(* Logix 5000 project; controller AMCI_5034_PTO_AM_Sample vendor 1 type 14 code 190 rev 37.11; software revision 37.00; part 3 of 3 *)

ADD_ON_INSTRUCTION AMCI_5034_PTO_AM_Registration   (* revision 1.0, vendor AMCI, ExecuteEnableInFalse *)
// AMCI Registration Move
// Revision note:
// 10/1/2025 Initial release of AOI.  Making the rung false will stop the registration move
// Help:
// Performs CW or CCW Registration Moves
// AXIS INPUT DATA:  Input data from the AMCI 5034-PTO-AM.   Uses the AMCI_5034_PTO_Input_Data User Defined Data Type.
// AXIS OUTPUT DATA; Output data from the AOI to the AMCI 5034-PTO-AM.    Uses the AMCI_5034_PTO_Output_Data User Defined Data Type.
// DIRECTION: 0 for Positve CW  or 1 for Negative CCW
// REGISTRATION_DISTANCE: Distance to move after the Registration Input has become active.
// TARGETVELOCITY: Speed of move in units of steps / sec
// ACCELERATION: Acceleration Rate in units of steps / sec / ms
// DECELERATION:  Deceleration Rate in units of steps / sec / ms
// EN (Enable) Set when rung is true, Reset when rung is false
// DN (Done) Set when command is sent to the motion device.  Reset when the rung is false.
// ER (Error) Set when a command, input. or configuration error.  Reset when the rung is false.
// IP (In Process) Set when motion is occurring.   Reset when motion stops or the rung goes false.
VAR_IN_OUT
   Axis_Input_Data : AMCI_5034_PTO_AM_Input_Data; {required}
   Axis_Output_Data : AMCI_5034_PTO_AM_Output_Data; {required}
END_VAR
VAR_INPUT
   Direction_0_PositiveCW_1_NegativeCCW : BOOL; {required}   // 0=jog CW 1=jog CCW
   _0_normal_1_S_Curve_Acceleration : BOOL;
   _0_Triangular_1_Trapezoidal_S_Curve : BOOL;
   Registration_Distance : DINT; {required}
   Programmed_Speed : DINT; {required}
   Acceleration : DINT; {required}
   Deceleration : INT; {required}
END_VAR
VAR_OUTPUT
   EN : BOOL; {visible}   // set when rung with AOI is true
   DN : BOOL; {access Read Only, visible}   // set when move was succesfully initiated
   ER : BOOL; {visible}
   IP : BOOL; {visible}   // set when motion occurring
END_VAR
VAR
   command_data_block : DINT[5];
        [0]   // Command Word
        [1]   // Target Positon
        [2]   // Programmed Speed
        [3]   // Acceleration
        [4]   // Deceleration
   motion_occurring : BOOL; {access None}
   Internal_Enable : BOOL; {access None}   // set when driver ready to receive motion command
END_VAR

ROUTINE EnableInFalse   (* ladder *)
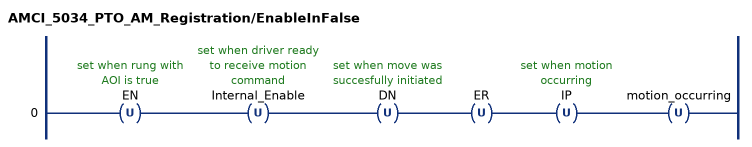
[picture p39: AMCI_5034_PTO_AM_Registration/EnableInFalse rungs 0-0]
   0: OTU(EN)OTU(Internal_Enable)OTU(DN)OTU(ER)OTU(IP)OTU(motion_occurring);
END_ROUTINE

ROUTINE Logic   (* ladder *)
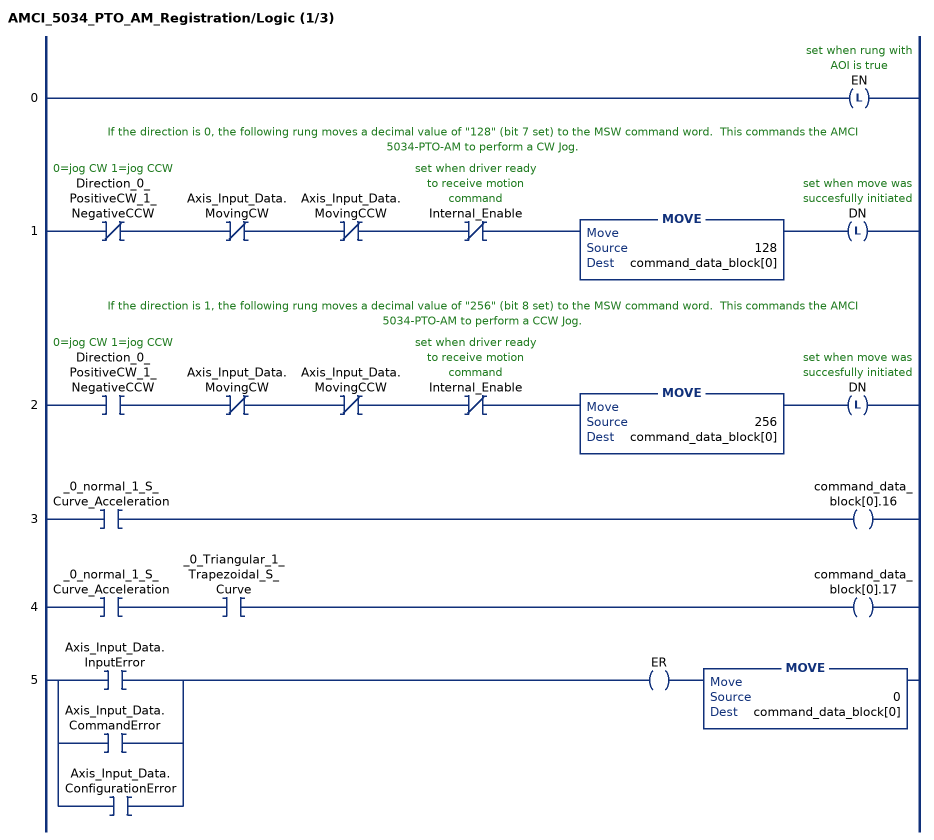
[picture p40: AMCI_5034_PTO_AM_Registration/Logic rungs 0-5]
   0: OTL(EN);
   // If the direction is 0, the following rung moves a decimal value of "128" (bit 7 set) to the MSW command word.  This commands the AMCI 5034-PTO-AM to perform a CW Jog.
   1: XIO(Direction_0_PositiveCW_1_NegativeCCW)XIO(Axis_Input_Data.MovingCW)XIO(Axis_Input_Data.MovingCCW)XIO(Internal_Enable)MOVE(128,command_data_block[0])OTL(DN);
   // If the direction is 1, the following rung moves a decimal value of "256" (bit 8 set) to the MSW command word.  This commands the AMCI 5034-PTO-AM to perform a CCW Jog.
   2: XIC(Direction_0_PositiveCW_1_NegativeCCW)XIO(Axis_Input_Data.MovingCW)XIO(Axis_Input_Data.MovingCCW)XIO(Internal_Enable)MOVE(256,command_data_block[0])OTL(DN);
   3: XIC(_0_normal_1_S_Curve_Acceleration)OTE(command_data_block[0].16);
   4: XIC(_0_normal_1_S_Curve_Acceleration)XIC(_0_Triangular_1_Trapezoidal_S_Curve)OTE(command_data_block[0].17);
   5: [XIC(Axis_Input_Data.InputError) ,XIC(Axis_Input_Data.CommandError) ,XIC(Axis_Input_Data.ConfigurationError) ]OTE(ER)MOVE(0,command_data_block[0]);
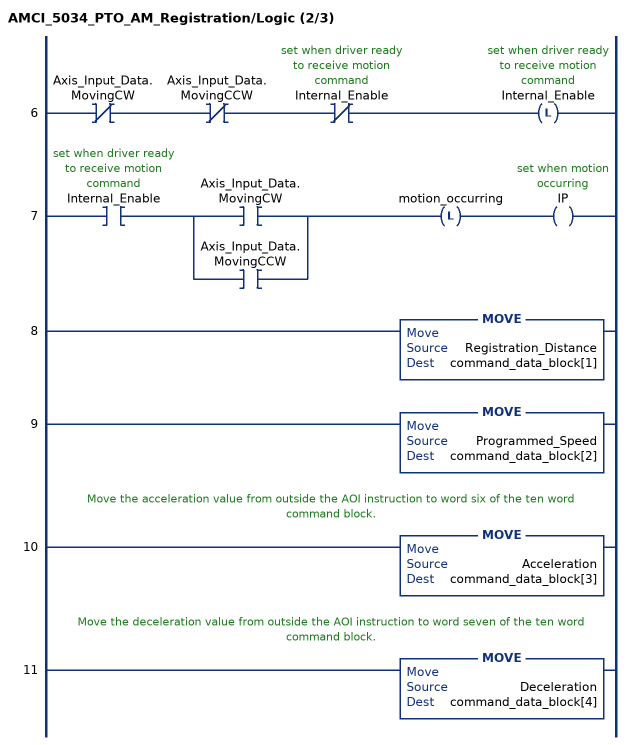
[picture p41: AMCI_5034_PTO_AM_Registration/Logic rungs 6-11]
   6: XIO(Axis_Input_Data.MovingCW)XIO(Axis_Input_Data.MovingCCW)XIO(Internal_Enable)OTL(Internal_Enable);
   7: XIC(Internal_Enable)[XIC(Axis_Input_Data.MovingCW) ,XIC(Axis_Input_Data.MovingCCW) ]OTL(motion_occurring)OTE(IP);
   8: MOVE(Registration_Distance,command_data_block[1]);
   9: MOVE(Programmed_Speed,command_data_block[2]);
   // Move the acceleration value from outside the AOI instruction to word six of the ten word command block.
   10: MOVE(Acceleration,command_data_block[3]);
   // Move the deceleration value from outside the AOI instruction to word seven of the ten word command block.
   11: MOVE(Deceleration,command_data_block[4]);
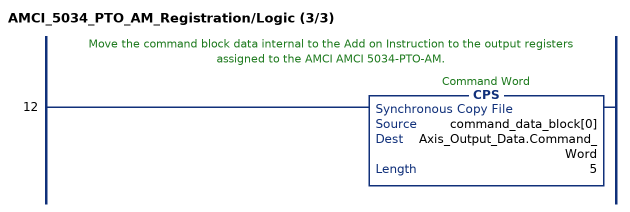
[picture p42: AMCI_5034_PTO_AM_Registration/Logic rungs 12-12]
   // Move the command block data internal to the Add on Instruction to the output registers assigned to the AMCI AMCI 5034-PTO-AM.
   12: CPS(command_data_block[0],Axis_Output_Data.Command_Word,5);
END_ROUTINE
END_ADD_ON_INSTRUCTION

ADD_ON_INSTRUCTION AMCI_5034_PTO_AM_Resume   (* revision 1.0, vendor AMCI, ExecuteEnableInFalse *)
// AMCI Resume
// Revision note:
// 10/01/2025 Initial Release
// Help:
// AXIS INPUT DATA:  Input data from the AMCI 5034-PTO-AM.   Uses the AMCI_5034_PTO_Input_Data User Defined Data Type.
// AXIS OUTPUT DATA; Output data from the AOI to the AMCI 5034-PTO-AM.    Uses the AMCI_5034_PTO_Output_Data User Defined Data Type.
// EN (Enable) Set when rung is true, Reset when rung is false
// DN (Done) Set when command is sent to the motion device.  Reset when the rung is false.
// ER (Error) Set when a command or input error.   Reset when the rung is false.
VAR_IN_OUT
   Axis_Input_Data : AMCI_5034_PTO_AM_Input_Data; {required}
   Axis_Output_Data : AMCI_5034_PTO_AM_Output_Data; {required}
END_VAR
VAR_OUTPUT
   EN : BOOL; {visible}   // set when rung with AOI is true
   DN : BOOL; {access Read Only, visible}   // set when reset error command sent to motion axis
   ER : BOOL; {access Read Only, visible}   // set when reset error command did not clear the error
END_VAR
VAR
   command_data_block : DINT[5];
        [0]   // Command Bits MSW
        [1]   // Command Bits LSW
        [2]   // Upper Target Position
        [3]   // Lower Target Position
        [4]   // Upper Programmed Speed
END_VAR

ROUTINE EnableInFalse   (* ladder *)
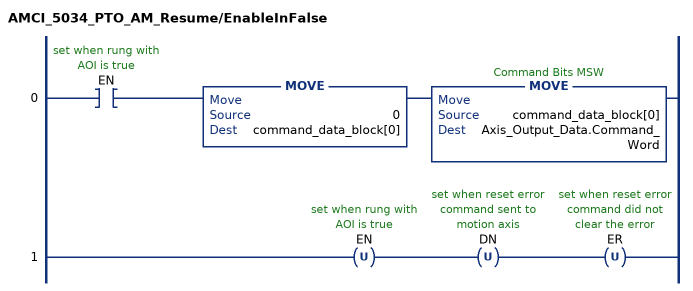
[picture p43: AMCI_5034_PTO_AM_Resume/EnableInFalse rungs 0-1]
   0: XIC(EN)MOVE(0,command_data_block[0])MOVE(command_data_block[0],Axis_Output_Data.Command_Word);
   1: OTU(EN)OTU(DN)OTU(ER);
END_ROUTINE

ROUTINE Logic   (* ladder *)
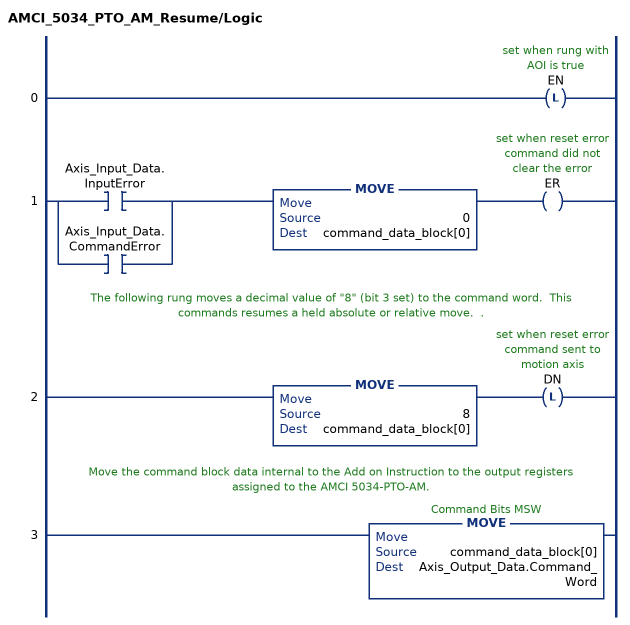
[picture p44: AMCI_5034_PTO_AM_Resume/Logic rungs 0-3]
   0: OTL(EN);
   1: [XIC(Axis_Input_Data.InputError) ,XIC(Axis_Input_Data.CommandError) ]MOVE(0,command_data_block[0])OTE(ER);
   // The following rung moves a decimal value of "8" (bit 3 set) to the command word.  This commands resumes a held absolute or relative move.  .
   2: MOVE(8,command_data_block[0])OTL(DN);
   // Move the command block data internal to the Add on Instruction to the output registers assigned to the AMCI 5034-PTO-AM.
   3: MOVE(command_data_block[0],Axis_Output_Data.Command_Word);
END_ROUTINE
END_ADD_ON_INSTRUCTION

ADD_ON_INSTRUCTION AMCI_5034_PTO_AM_Run_Blend   (* revision 1.0, vendor AMCI, ExecuteEnableInFalse *)
// Revision note:
// 10/01/2025 initial release
// Help:
// AXIS INPUT DATA:  Input data from the AMCI 5034-PTO-AM.   Uses the AMCI_5034_PTO_Input_Data User Defined Data Type.
// AXIS OUTPUT DATA; Output data from the AOI to the AMCI 5034-PTO-AM.    Uses the AMCI_5034_PTO_Output_Data User Defined Data Type.
// DIRECTION_0_POSITIVECW_1_NEGATIVECCW: Selects the direction in which the Blend Move will be run.
// EN (Enable) Set when rung is true, Reset when rung is false
// DN (Done) Set when command is sent to the motion device.  Reset when the rung is false.
// ER (Error) Set when a command, input, configuraiton, or profile error.   Reset when the rung is false.
VAR_IN_OUT
   Axis_Input_Data : AMCI_5034_PTO_AM_Input_Data; {required}
   Axis_Output_Data : AMCI_5034_PTO_AM_Output_Data; {required}
END_VAR
VAR_INPUT
   Direction_0_PositiveCW_1_NegativeCCW : BOOL; {required}
END_VAR
VAR_OUTPUT
   EN : BOOL; {visible}   // set when rung with AOI is true and the Move Complete stetus bit is off.
   DN : BOOL; {access Read Only, visible}   // set when preset motor position command sent to motion axis
   ER : BOOL; {access Read Only, visible}   // set when input, command, or configuraiton error
END_VAR
VAR
   command_data_block : DINT[5];
        [0]   // Command Bits MSW
        [1]   // Target Position
        [2]   // Upper Target Position
        [3]   // Lower Target Position
        [4]   // Upper Programmed Speed
END_VAR

ROUTINE EnableInFalse   (* ladder *)
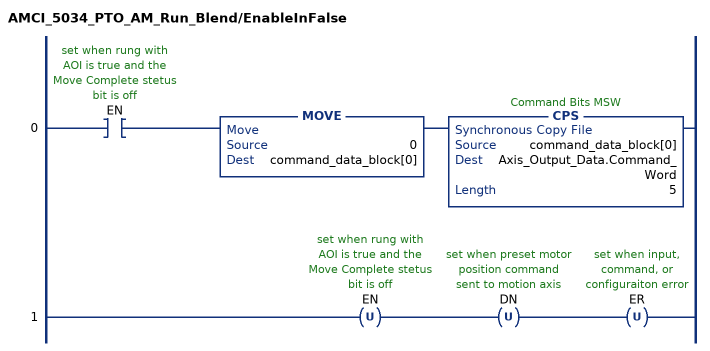
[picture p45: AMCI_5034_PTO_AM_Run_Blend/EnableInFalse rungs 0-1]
   0: XIC(EN)MOVE(0,command_data_block[0])CPS(command_data_block[0],Axis_Output_Data.Command_Word,5);
   1: OTU(EN)OTU(DN)OTU(ER);
END_ROUTINE

ROUTINE Logic   (* ladder *)
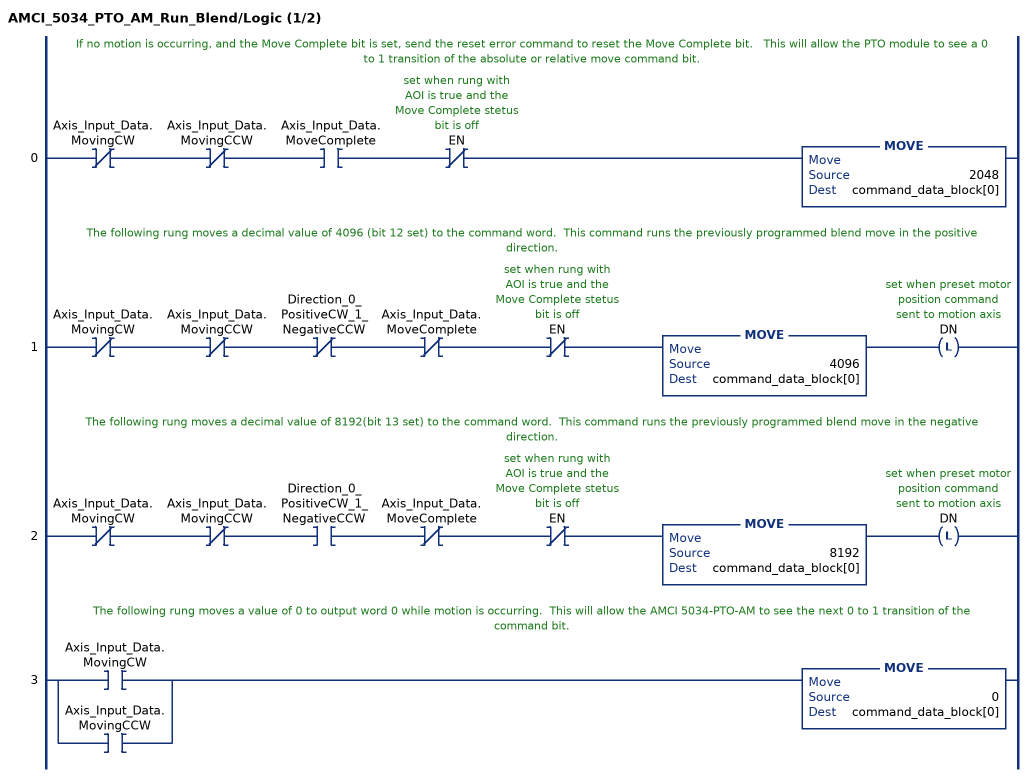
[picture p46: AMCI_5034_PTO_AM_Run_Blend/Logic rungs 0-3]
   // If no motion is occurring, and the Move Complete bit is set, send the reset error command to reset the Move Complete bit.   This will allow the PTO module to see a 0 to 1 transition of the absolute or relative move command bit.
   0: XIO(Axis_Input_Data.MovingCW)XIO(Axis_Input_Data.MovingCCW)XIC(Axis_Input_Data.MoveComplete)XIO(EN)MOVE(2048,command_data_block[0]);
   // The following rung moves a decimal value of 4096 (bit 12 set) to the command word.  This command runs the previously programmed blend move in the positive direction.
   1: XIO(Axis_Input_Data.MovingCW)XIO(Axis_Input_Data.MovingCCW)XIO(Direction_0_PositiveCW_1_NegativeCCW)XIO(Axis_Input_Data.MoveComplete)XIO(EN)MOVE(4096,command_data_block[0])OTL(DN);
   // The following rung moves a decimal value of 8192(bit 13 set) to the command word.  This command runs the previously programmed blend move in the negative direction.
   2: XIO(Axis_Input_Data.MovingCW)XIO(Axis_Input_Data.MovingCCW)XIC(Direction_0_PositiveCW_1_NegativeCCW)XIO(Axis_Input_Data.MoveComplete)XIO(EN)MOVE(8192,command_data_block[0])OTL(DN);
   // The following rung moves a value of 0 to output word 0 while motion is occurring.  This will allow the AMCI 5034-PTO-AM to see the next 0 to 1 transition of the command bit.
   3: [XIC(Axis_Input_Data.MovingCW) ,XIC(Axis_Input_Data.MovingCCW) ]MOVE(0,command_data_block[0]);
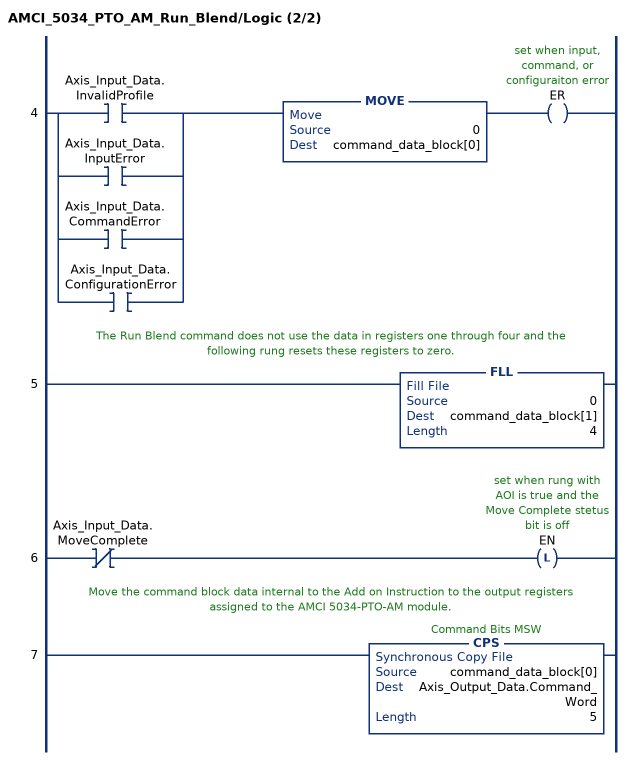
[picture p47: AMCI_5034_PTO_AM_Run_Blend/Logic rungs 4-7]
   4: [XIC(Axis_Input_Data.InvalidProfile) ,XIC(Axis_Input_Data.InputError) ,XIC(Axis_Input_Data.CommandError) ,XIC(Axis_Input_Data.ConfigurationError) ]MOVE(0,command_data_block[0])OTE(ER);
   // The Run Blend command does not use the data in registers one through four and the following rung resets these registers to zero.
   5: FLL(0,command_data_block[1],4);
   6: XIO(Axis_Input_Data.MoveComplete)OTL(EN);
   // Move the command block data internal to the Add on Instruction to the output registers assigned to the AMCI 5034-PTO-AM module.
   7: CPS(command_data_block[0],Axis_Output_Data.Command_Word,5);
END_ROUTINE
END_ADD_ON_INSTRUCTION

ADD_ON_INSTRUCTION AMCI_5034_PTO_AM_Stop_Jog   (* revision 1.0, vendor AMCI, ExecuteEnableInFalse *)
// AMCI Stop Jog
// Revision note:
// 10/01/2025 Initial Release
// Help:
// AXIS INPUT DATA:  Input data from the AMCI 5034-PTO-AM.   Uses the AMCI_5034_PTO_Input_Data User Defined Data Type.
// AXIS OUTPUT DATA; Output data from the AOI to the AMCI 5034-PTO-AM.    Uses the AMCI_5034_PTO_Output_Data User Defined Data Type.
// EN (Enable) Set when rung is true, Reset when rung is false
// DN (Done) Set when command is sent to the motion device.  Reset when the rung is false.
// ER (Error) Set when there is a command or input error.  Reset when the rung is false.
VAR_IN_OUT
   Axis_Input_Data : AMCI_5034_PTO_AM_Input_Data; {required}
   Axis_Output_Data : AMCI_5034_PTO_AM_Output_Data; {required}
END_VAR
VAR_OUTPUT
   EN : BOOL; {visible}   // set when rung with AOI is true
   DN : BOOL; {access Read Only, visible}   // set when reset error command sent to motion axis
   ER : BOOL; {access Read Only, visible}   // set when reset error command did not clear the error
END_VAR
VAR
   command_data_block : DINT[5];
        [0]   // Command Bits MSW
        [1]   // Command Bits LSW
        [2]   // Upper Target Position
        [3]   // Lower Target Position
        [4]   // Upper Programmed Speed
END_VAR

ROUTINE EnableInFalse   (* ladder *)
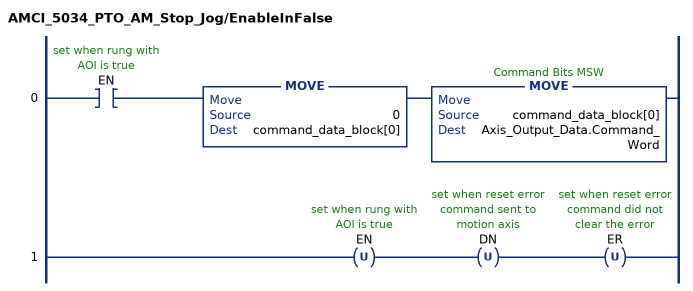
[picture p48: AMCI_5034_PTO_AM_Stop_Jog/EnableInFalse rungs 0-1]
   0: XIC(EN)MOVE(0,command_data_block[0])MOVE(command_data_block[0],Axis_Output_Data.Command_Word);
   1: OTU(EN)OTU(DN)OTU(ER);
END_ROUTINE

ROUTINE Logic   (* ladder *)
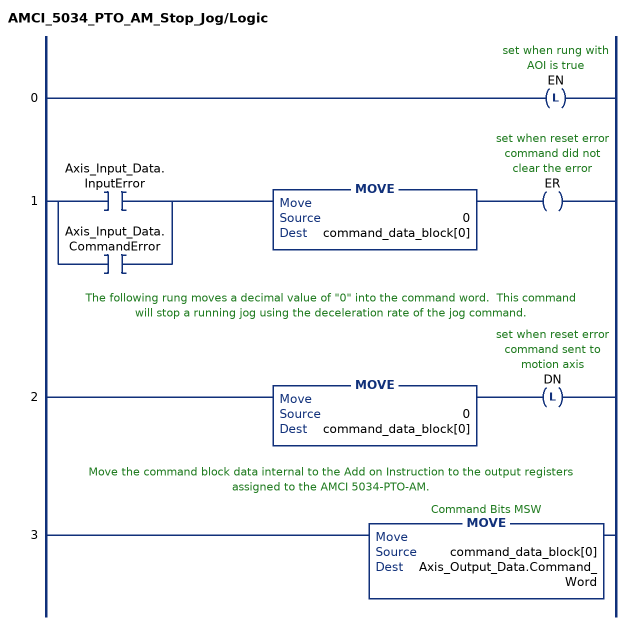
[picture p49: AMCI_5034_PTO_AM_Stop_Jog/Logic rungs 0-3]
   0: OTL(EN);
   1: [XIC(Axis_Input_Data.InputError) ,XIC(Axis_Input_Data.CommandError) ]MOVE(0,command_data_block[0])OTE(ER);
   // The following rung moves a decimal value of "0" into the command word.  This command will stop a running jog using the deceleration rate of the jog command.
   2: MOVE(0,command_data_block[0])OTL(DN);
   // Move the command block data internal to the Add on Instruction to the output registers assigned to the AMCI 5034-PTO-AM.
   3: MOVE(command_data_block[0],Axis_Output_Data.Command_Word);
END_ROUTINE
END_ADD_ON_INSTRUCTION

VAR_GLOBAL   (* controller tags *)
   AMCI_Input_Data_5034_PTO_AM : AMCI_5034_PTO_AM_Input_Data;
   AMCI_Output_Data_5034_PTO_AM : AMCI_5034_PTO_AM_Output_Data;
   run_AMCI_5034_PTO_AM : DINT;
        .0   // Relative Move
        .3   // Stop Jog
        .4   // Reset Errors
        .5   // Preset Current Position
        .1   // Absolute Move
        .6   // Home CW or Home CCW
        .7   // Program Blend
        .8   // Run Blend CW or Run Blend CCW
        .2   // Jog CW or Jog CCW
END_VAR

PROGRAM MainProgram   (* main routine MainRoutine *)
VAR
   AMCI_MAFR_5034_PTO_AM : AMCI_5034_PTO_AM_MAFR;
   AMCI_MAH_5034_PTO_AM : AMCI_5034_PTO_AM_MAH;
   AMCI_MAJ_5034_PTO_AM : AMCI_5034_PTO_AM_MAJ;
   AMCI_MAM_Absolute_Move_5034_PTO_AM : AMCI_5034_PTO_AM_MAM;
   AMCI_MAM_Relative_Move_5034_PTO_AM : AMCI_5034_PTO_AM_MAM;
   AMCI_MRP_5034_PTO_AM : AMCI_5034_PTO_AM_MRP;
   AMCI_Program_Blend_5034_PTO_AM : AMCI_5034_PTO_AM_Program_Blend_Move;
   AMCI_Run_Blend_5034_PTO_AM : AMCI_5034_PTO_AM_Run_Blend;
   AMCI_Stop_Jog_5034_PTO_AM : AMCI_5034_PTO_AM_Stop_Jog;
END_VAR

ROUTINE MainRoutine   (* ladder *)
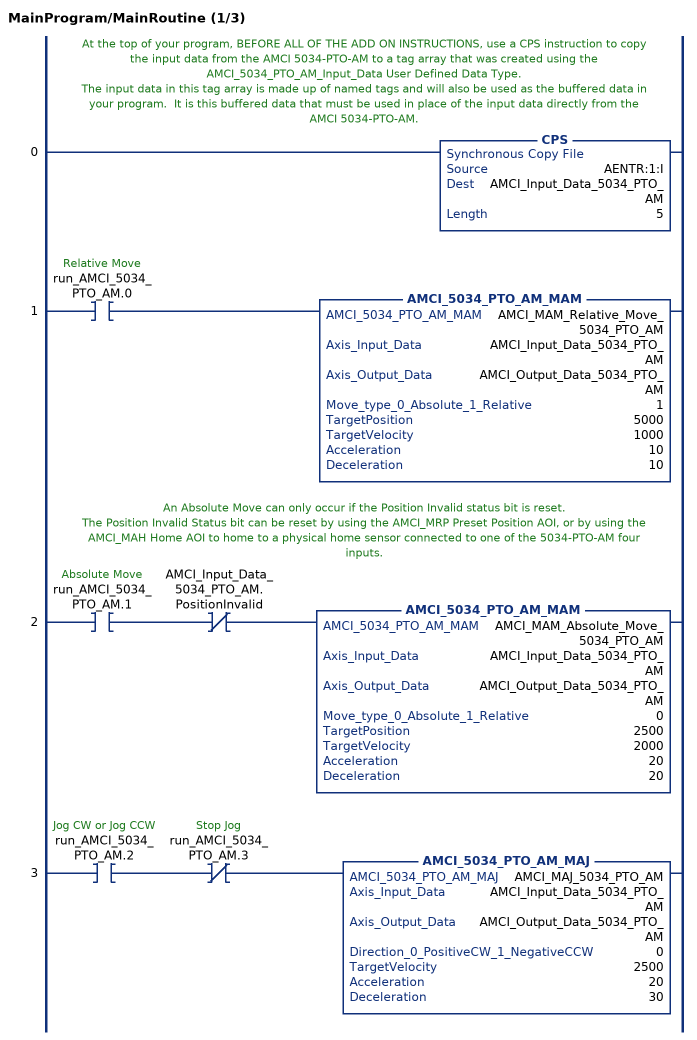
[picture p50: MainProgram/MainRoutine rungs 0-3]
   // At the top of your program, BEFORE ALL OF THE ADD ON INSTRUCTIONS, use a CPS instruction to copy the input data from the AMCI 5034-PTO-AM to a tag array that was created using the AMCI_5034_PTO_AM_Input_Data User Defined Data Type.
   // The input data in this tag array is made up of named tags and will also be used as the buffered data in your program.  It is this buffered data that must be used in place of the input data directly from the AMCI 5034-PTO-AM.
   0: CPS(AENTR:1:I,AMCI_Input_Data_5034_PTO_AM,5);
   1: XIC(run_AMCI_5034_PTO_AM.0)AMCI_5034_PTO_AM_MAM(AMCI_MAM_Relative_Move_5034_PTO_AM,AMCI_Input_Data_5034_PTO_AM,AMCI_Output_Data_5034_PTO_AM,1,5000,1000,10,10);
   // An Absolute Move can only occur if the Position Invalid status bit is reset.
   // The Position Invalid Status bit can be reset by using the AMCI_MRP Preset Position AOI, or by using the AMCI_MAH Home AOI to home to a physical home sensor connected to one of the 5034-PTO-AM four inputs.
   2: XIC(run_AMCI_5034_PTO_AM.1)XIO(AMCI_Input_Data_5034_PTO_AM.PositionInvalid)AMCI_5034_PTO_AM_MAM(AMCI_MAM_Absolute_Move_5034_PTO_AM,AMCI_Input_Data_5034_PTO_AM,AMCI_Output_Data_5034_PTO_AM,0,2500,2000,20,20);
   3: XIC(run_AMCI_5034_PTO_AM.2)XIO(run_AMCI_5034_PTO_AM.3)AMCI_5034_PTO_AM_MAJ(AMCI_MAJ_5034_PTO_AM,AMCI_Input_Data_5034_PTO_AM,AMCI_Output_Data_5034_PTO_AM,0,2500,20,30);
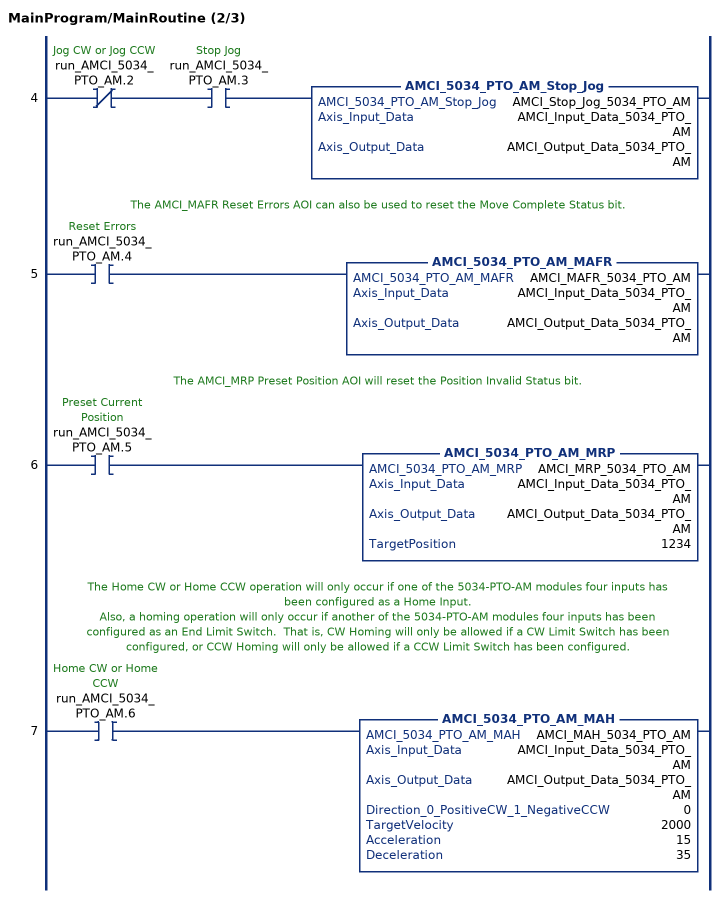
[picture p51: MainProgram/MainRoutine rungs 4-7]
   4: XIO(run_AMCI_5034_PTO_AM.2)XIC(run_AMCI_5034_PTO_AM.3)AMCI_5034_PTO_AM_Stop_Jog(AMCI_Stop_Jog_5034_PTO_AM,AMCI_Input_Data_5034_PTO_AM,AMCI_Output_Data_5034_PTO_AM);
   // The AMCI_MAFR Reset Errors AOI can also be used to reset the Move Complete Status bit.
   5: XIC(run_AMCI_5034_PTO_AM.4)AMCI_5034_PTO_AM_MAFR(AMCI_MAFR_5034_PTO_AM,AMCI_Input_Data_5034_PTO_AM,AMCI_Output_Data_5034_PTO_AM);
   // The AMCI_MRP Preset Position AOI will reset the Position Invalid Status bit.
   6: XIC(run_AMCI_5034_PTO_AM.5)AMCI_5034_PTO_AM_MRP(AMCI_MRP_5034_PTO_AM,AMCI_Input_Data_5034_PTO_AM,AMCI_Output_Data_5034_PTO_AM,1234);
   // The Home CW or Home CCW operation will only occur if one of the 5034-PTO-AM modules four inputs has been configured as a Home Input.
   // Also, a homing operation will only occur if another of the 5034-PTO-AM modules four inputs has been configured as an End Limit Switch.  That is, CW Homing will only be allowed if a CW Limit Switch has been configured, or CCW Homing will only be allowed if a CCW Limit Switch has been configured.
   7: XIC(run_AMCI_5034_PTO_AM.6)AMCI_5034_PTO_AM_MAH(AMCI_MAH_5034_PTO_AM,AMCI_Input_Data_5034_PTO_AM,AMCI_Output_Data_5034_PTO_AM,0,2000,15,35);
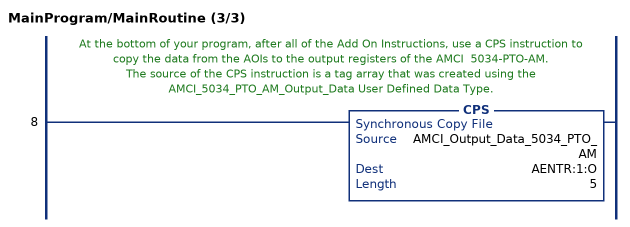
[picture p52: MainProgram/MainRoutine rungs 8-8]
   // At the bottom of your program, after all of the Add On Instructions, use a CPS instruction to copy the data from the AOIs to the output registers of the AMCI  5034-PTO-AM.
   // The source of the CPS instruction is a tag array that was created using the AMCI_5034_PTO_AM_Output_Data User Defined Data Type.
   8: CPS(AMCI_Output_Data_5034_PTO_AM,AENTR:1:O,5);
END_ROUTINE

ROUTINE Program_Run_Blend   (* ladder *)
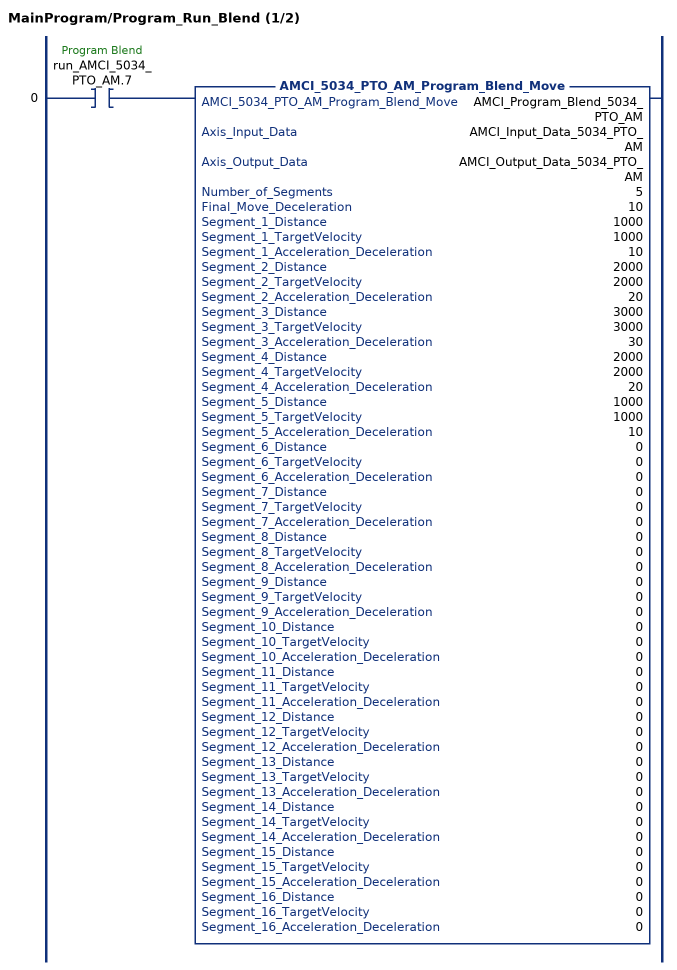
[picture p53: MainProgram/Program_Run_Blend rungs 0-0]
   0: XIC(run_AMCI_5034_PTO_AM.7)AMCI_5034_PTO_AM_Program_Blend_Move(AMCI_Program_Blend_5034_PTO_AM,AMCI_Input_Data_5034_PTO_AM,AMCI_Output_Data_5034_PTO_AM,5,10,1000,1000,10,2000,2000,20,3000,3000,30,2000,2000,20,1000,1000,10,0,0,0,0,0,0,0,0,0,0,0,0,0,0,0,0,0,0,0,0,0,0,0,0,0,0,0,0,0,0,0,0,0);
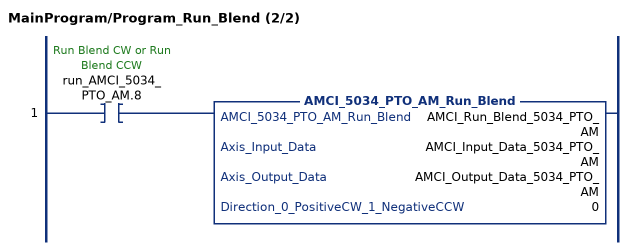
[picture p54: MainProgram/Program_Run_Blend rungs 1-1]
   1: XIC(run_AMCI_5034_PTO_AM.8)AMCI_5034_PTO_AM_Run_Blend(AMCI_Run_Blend_5034_PTO_AM,AMCI_Input_Data_5034_PTO_AM,AMCI_Output_Data_5034_PTO_AM,0);
END_ROUTINE
END_PROGRAM
